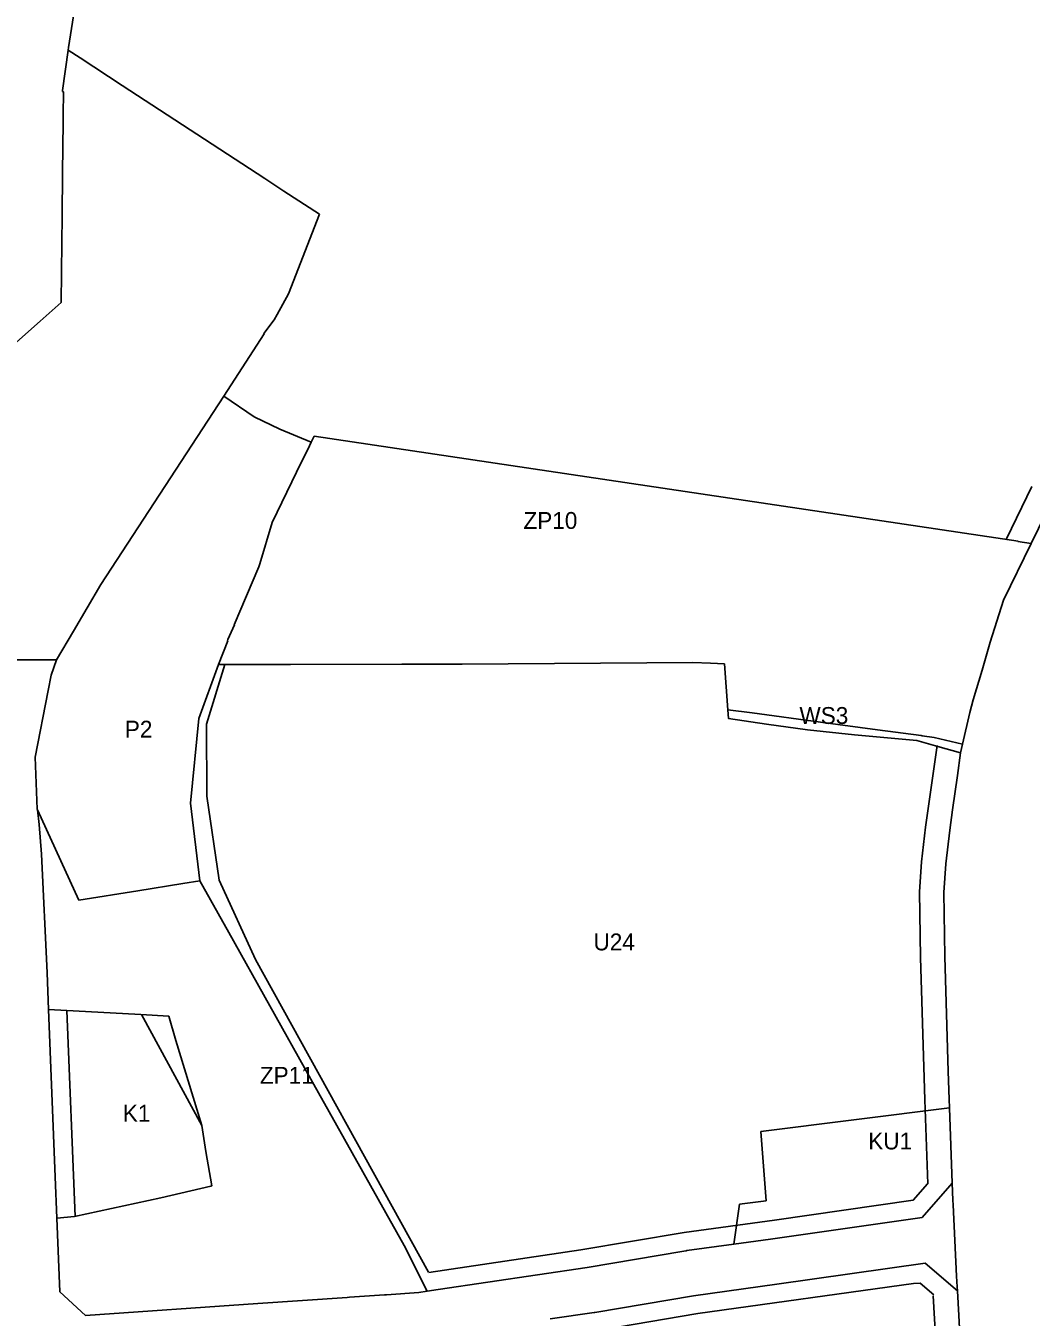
# Model space of a CAD drawing. Extents: x 7428080 to 7432143, y 5545880 to 5549217.
# Drawn here: x 7429886.6 to 7430217.3, y 5548060 to 5548484.5 of the extents above; entities that cross this region are included whole.
import ezdxf

# ---------------------------------------------------------------- set-up
doc = ezdxf.new("R2010")
doc.units = 0
for name, color, linetype in [('CZ_L_linie rozgraniczające tereny o różnym przeznaczeniu oraz różnych warunkach ich zabudowy i zagospodarowania', 7, 'Continuous'), ('CZ_L_maksymalne nieprzekraczalne linie zabudowy', 7, 'Continuous'), ('CZ_L_opisy_linie rozgraniczające tereny o różnym przeznaczeniu oraz różnych warunkach ich zabudowy i zagospodarowania', 7, 'Continuous')]:
    doc.layers.add(name, color=color, linetype=linetype)

msp = doc.modelspace()

# ---------------------------------------------------------------- linework, layer by layer
at = {"layer": 'CZ_L_linie rozgraniczające tereny o różnym przeznaczeniu oraz różnych warunkach ich zabudowy i zagospodarowania'}
for p, q in [((7429900.68, 5548477.42), (7429904, 5548498.36)), ((7429900.56, 5548476.55), (7429900.68, 5548477.42)), ((7429898.74, 5548463.27), (7429900.56, 5548476.55)), ((7429904.49, 5548473.97), (7429900.56, 5548476.55)), ((7429918.28, 5548464.92), (7429904.49, 5548473.97)), ((7429918.28, 5548464.91), (7429918.28, 5548464.92)), ((7429965.25, 5548434.31), (7429918.28, 5548464.91)), ((7429898.7, 5548462.98), (7429898.74, 5548463.27)), ((7429899.02, 5548462.88), (7429898.7, 5548462.98)), ((7429898.94, 5548455.18), (7429899.02, 5548462.88)), ((7429898.75, 5548436.19), (7429898.92, 5548453.02)), ((7429898.92, 5548453.02), (7429898.94, 5548455.18)), ((7429898.6, 5548421.9), (7429898.75, 5548436.19)), ((7429971.53, 5548430.21), (7429965.25, 5548434.31)), ((7429983.18, 5548422.62), (7429971.53, 5548430.21)), ((7429973, 5548396.44), (7429983.18, 5548422.62)), ((7429898.52, 5548413.33), (7429898.6, 5548421.9)), ((7429898.32, 5548393.62), (7429898.52, 5548413.33)), ((7429891.41, 5548387.5), (7429898.32, 5548393.62)), ((7429969.27, 5548389.59), (7429973, 5548396.44)), ((7429968.33, 5548387.85), (7429969.27, 5548389.59)), ((7429882.63, 5548379.71), (7429891.41, 5548387.5)), ((7429964.89, 5548383.37), (7429968.33, 5548387.85)), ((7429951.71, 5548362.8), (7429965.07, 5548383.26)), ((7429965.07, 5548383.26), (7429964.89, 5548383.37)), ((7429951.71, 5548362.8), (7429911.31, 5548300.91)), ((7429961.77, 5548356.02), (7429951.71, 5548362.8)), ((7429970.22, 5548351.93), (7429961.77, 5548356.02)), ((7429980.47, 5548347.63), (7429970.22, 5548351.93)), ((7429979.34, 5548345.31), (7429980.47, 5548347.63)), ((7429981.46, 5548349.67), (7429980.47, 5548347.63)), ((7430212.99, 5548315.17), (7429981.46, 5548349.67)), ((7429977.33, 5548341.17), (7429979.34, 5548345.31)), ((7429967.64, 5548321.22), (7429977.33, 5548341.17)), ((7430224.45, 5548329.12), (7430217.23, 5548314.32)), ((7429963.59, 5548307.67), (7429967.64, 5548321.22)), ((7430217.23, 5548314.32), (7430208.15, 5548295.69)), ((7430212.91, 5548315.01), (7430212.99, 5548315.17)), ((7430217.23, 5548314.32), (7430212.91, 5548315.01)), ((7429963.28, 5548306.64), (7429963.59, 5548307.67)), ((7429955.17, 5548287.65), (7429963.28, 5548306.64)), ((7429911.31, 5548300.91), (7429902.3, 5548285.56)), ((7430208.15, 5548295.69), (7430203.82, 5548281.96)), ((7429953.1, 5548282.8), (7429955.31, 5548287.65)), ((7429955.31, 5548287.65), (7429955.17, 5548287.65)), ((7429902.3, 5548285.56), (7429896.76, 5548276.15)), ((7429950.02, 5548274.53), (7429953.08, 5548282.4)), ((7429952.93, 5548282.41), (7429953.07, 5548282.8)), ((7429953.08, 5548282.4), (7429952.93, 5548282.41)), ((7429953.07, 5548282.8), (7429953.1, 5548282.8)), ((7430203.82, 5548281.96), (7430201.1, 5548272.72)), ((7429896.76, 5548276.15), (7429856.01, 5548276.02)), ((7429895.01, 5548271.04), (7429896.76, 5548276.15)), ((7429943.51, 5548256.83), (7429950.02, 5548274.53)), ((7429950.02, 5548274.53), (7429952.04, 5548274.53)), ((7429952.04, 5548274.53), (7429973.7, 5548274.58)), ((7429973.7, 5548274.58), (7430010.32, 5548274.66)), ((7430010.32, 5548274.66), (7430030.1, 5548274.7)), ((7430030.1, 5548274.7), (7430106, 5548275.27)), ((7430106, 5548275.27), (7430111.79, 5548275.03)), ((7430111.79, 5548275.03), (7430116.43, 5548274.83)), ((7430116.43, 5548274.83), (7430117.56, 5548259.73)), ((7429894.04, 5548266.06), (7429895.01, 5548271.04)), ((7430201.1, 5548272.72), (7430198.23, 5548262.99)), ((7429889.76, 5548244.08), (7429894.04, 5548266.06)), ((7430198.23, 5548262.99), (7430197.07, 5548258.75)), ((7429940.84, 5548228.99), (7429943.51, 5548256.83)), ((7430125.5, 5548258.65), (7430117.56, 5548259.73)), ((7430147.99, 5548255.62), (7430125.5, 5548258.65)), ((7430197.07, 5548258.75), (7430194.69, 5548248.36)), ((7430166.77, 5548253.11), (7430147.99, 5548255.62)), ((7430181.07, 5548251.2), (7430166.77, 5548253.11)), ((7430181.45, 5548251.13), (7430181.07, 5548251.2)), ((7430185.4, 5548250.61), (7430181.45, 5548251.13)), ((7430194.69, 5548248.36), (7430185.4, 5548250.61)), ((7430194.69, 5548248.36), (7430194.06, 5548245.59)), ((7429890.38, 5548227.06), (7429889.76, 5548244.08)), ((7430194.06, 5548245.59), (7430193.01, 5548238.09)), ((7430193.01, 5548238.09), (7430191.43, 5548226.76)), ((7429890.5, 5548226.8), (7429890.38, 5548227.06)), ((7429891.04, 5548222), (7429890.5, 5548226.8)), ((7429890.5, 5548226.8), (7429904.1, 5548197.11)), ((7429943.82, 5548203.5), (7429940.84, 5548228.99)), ((7430191.43, 5548226.76), (7430190.5, 5548220.15)), ((7429891.82, 5548212.26), (7429891.04, 5548222)), ((7430190.5, 5548220.15), (7430189.22, 5548209.03)), ((7429893.61, 5548173.2), (7429891.82, 5548212.26)), ((7430189.22, 5548209.03), (7430188.5, 5548199.62)), ((7429923.44, 5548200.17), (7429938.23, 5548202.63)), ((7429938.23, 5548202.63), (7429943.82, 5548203.5)), ((7429953.36, 5548186.48), (7429943.82, 5548203.5)), ((7429904.1, 5548197.11), (7429923.44, 5548200.17)), ((7430188.5, 5548199.62), (7430188.83, 5548178.55)), ((7429980.38, 5548138.29), (7429953.36, 5548186.48)), ((7430188.83, 5548178.55), (7430189.99, 5548140.74)), ((7429894.09, 5548161.22), (7429893.61, 5548173.2)), ((7429896.29, 5548106.13), (7429894.09, 5548161.22)), ((7429894.09, 5548161.22), (7429924.42, 5548159.49)), ((7429924.42, 5548159.49), (7429933.62, 5548158.97)), ((7429933.62, 5548158.97), (7429936.03, 5548150.99)), ((7429936.03, 5548150.99), (7429944.49, 5548123)), ((7430011.07, 5548083.54), (7429980.38, 5548138.29)), ((7430189.99, 5548140.74), (7430190.26, 5548131.75)), ((7430190.26, 5548131.75), (7430190.37, 5548128.86)), ((7430190.37, 5548128.86), (7430128.38, 5548121.04)), ((7430190.37, 5548128.86), (7430191.3, 5548104.13)), ((7429944.49, 5548123), (7429945.82, 5548114.54)), ((7430128.38, 5548121.04), (7430130.16, 5548098.26)), ((7429945.82, 5548114.54), (7429947.79, 5548103.21)), ((7429896.84, 5548092.61), (7429896.29, 5548106.13)), ((7430191.3, 5548104.13), (7430181.44, 5548092.75)), ((7430191.51, 5548098.46), (7430191.3, 5548104.13)), ((7429947.51, 5548103.15), (7429931.08, 5548099.27)), ((7429947.79, 5548103.21), (7429947.51, 5548103.15)), ((7429931.08, 5548099.27), (7429902.65, 5548093.16)), ((7430121.31, 5548097.17), (7430119.43, 5548084.03)), ((7430130.16, 5548098.26), (7430121.31, 5548097.17)), ((7430191.57, 5548096.98), (7430191.51, 5548098.46)), ((7430192.74, 5548073.53), (7430191.57, 5548096.98)), ((7429902.65, 5548093.16), (7429896.84, 5548092.61)), ((7429897.82, 5548068.32), (7429896.84, 5548092.61)), ((7430181.44, 5548092.75), (7430131.58, 5548085.69)), ((7430018.58, 5548068.58), (7430011.07, 5548083.54)), ((7430119.43, 5548084.03), (7430104.07, 5548081.93)), ((7430131.58, 5548085.69), (7430119.43, 5548084.03)), ((7430103.02, 5548081.76), (7430071.3, 5548076.41)), ((7430103.84, 5548081.89), (7430103.02, 5548081.76)), ((7430104.07, 5548081.93), (7430103.84, 5548081.89)), ((7430071.3, 5548076.41), (7430022.24, 5548069.12)), ((7430133.65, 5548070.84), (7430182.38, 5548077.74)), ((7430182.38, 5548077.74), (7430192.99, 5548068.68)), ((7430106.21, 5548067.08), (7430133.62, 5548070.83)), ((7430133.62, 5548070.83), (7430133.65, 5548070.84)), ((7430192.91, 5548070.03), (7430192.74, 5548073.53)), ((7430192.99, 5548068.68), (7430192.91, 5548070.03)), ((7429906.23, 5548060.63), (7429897.82, 5548068.32)), ((7429992.31, 5548066.53), (7429962.95, 5548064.49)), ((7429993.07, 5548066.59), (7429992.31, 5548066.53)), ((7430004.6, 5548067.39), (7429993.07, 5548066.59)), ((7430005.22, 5548067.43), (7430004.6, 5548067.39)), ((7430015.87, 5548068.17), (7430005.22, 5548067.43)), ((7430018.58, 5548068.58), (7430015.87, 5548068.17)), ((7430022.24, 5548069.12), (7430018.58, 5548068.58)), ((7430073.72, 5548061.61), (7430106.21, 5548067.08)), ((7430192.99, 5548068.68), (7430195.61, 5548021.96)), ((7429962.95, 5548064.49), (7429906.23, 5548060.63)), ((7430059.1, 5548059.44), (7430073.57, 5548061.59)), ((7430073.57, 5548061.59), (7430073.72, 5548061.61))]:
    msp.add_line(p, q, dxfattribs=at)
for points in [[(7430117.56, 5548259.73), (7430117.55, 5548259.73)], [(7430117.55, 5548259.73), (7430117.78, 5548256.79), (7430130.25, 5548255.01), (7430143.72, 5548253.16), (7430159.11, 5548251.49), (7430179.63, 5548249.59), (7430186.61, 5548247.65), (7430194.06, 5548245.59)]]:
    msp.add_lwpolyline(points, dxfattribs=at)
at = {"layer": 'CZ_L_maksymalne nieprzekraczalne linie zabudowy'}
for points in [[(7430209.1, 5548315.89), (7430217.49, 5548333.07)], [(7429952.08, 5548274.53), (7429946.08, 5548254.96), (7429946.22, 5548231.33), (7429950.28, 5548203.72), (7429962.18, 5548177.62), (7430019.07, 5548074.85)], [(7430183.3, 5548103.86), (7430182.27, 5548131.5), (7430180.84, 5548178.31), (7430180.5, 5548199.81), (7430181.25, 5548209.75), (7430182.55, 5548221.08), (7430186.4, 5548247.99)], [(7429900.11, 5548160.85), (7429902.82, 5548093.18)], [(7429944.49, 5548123), (7429924.73, 5548159.48)], [(7430019.23, 5548074.74), (7430069.16, 5548082.16), (7430103.17, 5548087.86), (7430132.86, 5548091.93), (7430178.48, 5548098.5), (7430183.12, 5548103.86)], [(7430185.29, 5548067.36), (7430180.79, 5548071.2), (7430178.6, 5548071.14), (7430107.69, 5548061.23), (7430076.06, 5548055.92), (7430039.24, 5548050.42), (7430038.47, 5548048.77), (7430038.85, 5548042.83)], [(7430154.46, 5547785.67), (7430173.26, 5547792.27), (7430193.23, 5547799.51), (7430194.45, 5547800.07), (7430198.73, 5547806.16), (7430199.09, 5547838.74), (7430198.96, 5547850.56), (7430197.64, 5547869.4), (7430193.56, 5547919.92), (7430185.06, 5548067.1)]]:
    msp.add_lwpolyline(points, dxfattribs=at)

# ---------------------------------------------------------------- texts
at = {"layer": 'CZ_L_opisy_linie rozgraniczające tereny o różnym przeznaczeniu oraz różnych warunkach ich zabudowy i zagospodarowania'}
for s, p in [('ZP10', (7430050.29, 5548319.15)), ('WS3', (7430141.05, 5548255.04)), ('P2', (7429919.2, 5548250.55)), ('U24', (7430073.32, 5548180.61)), ('ZP11', (7429963.61, 5548136.76)), ('K1', (7429918.53, 5548124.3)), ('KU1', (7430163.68, 5548115.17))]:
    msp.add_text(s, height=5.549, dxfattribs=at).set_placement(p)

doc.saveas('drawing.dxf')
